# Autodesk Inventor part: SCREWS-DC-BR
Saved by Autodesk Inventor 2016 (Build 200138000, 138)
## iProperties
Created: 2015-09
Part Number: SCREWS-DC-BR
Material: Generic
Document SubType Name: Modeling
Designer: irish_000
Density: 1 g/cm^3
Appearance: Default
Author: irish_000
Revision Number: ANY
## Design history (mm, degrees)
fillet "Fillet2"
body "Solid1"
